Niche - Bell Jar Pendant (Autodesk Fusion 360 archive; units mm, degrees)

design "Bell Jar" references "Niche - Chief Architect - Luxe Single Pendant Cordset", "Bell Jar", "Luxe Single Pendant Cordset - 4ft Standard"
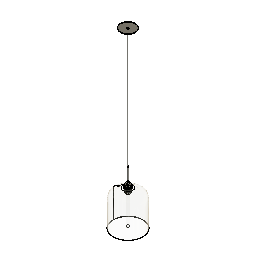
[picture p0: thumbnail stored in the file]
external_derived "ExternalDerived1"
external_derived "ExternalDerived2" bodies "Socket Body", "Shade Ring", "Shade Ring +Collar", "Socket", "Body1", "Metal Strain Relief", "Fabric Cord (1)", "Stem (Threaded)"
move "Move1"
external_derived "ExternalDerived3" bodies "T8-Bulb"
move "Move2"
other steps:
derived_base_feature "Derived Base Feature1" bodies "Bell Jar"
derived_base_feature "Derived Base Feature2" bodies "Socket Body", "Shade Ring", "Shade Ring +Collar", "Socket", "Body1", "Metal Strain Relief", "Fabric Cord (1)", "Stem (Threaded)"
derived_base_feature "Derived Base Feature3" bodies "T8-Bulb"
named bodies: "Bell Jar", "Socket Body", "Shade Ring", "Shade Ring +Collar", "Socket", "Body1", "Metal Strain Relief", "Fabric Cord (1)", "Stem (Threaded)", "Cap (Threaded)", "T8-Bulb"

design "Luxe Single Pendant Cordset - 4ft Standard" references "Luxe Canopy - Single Pendant Cordset"
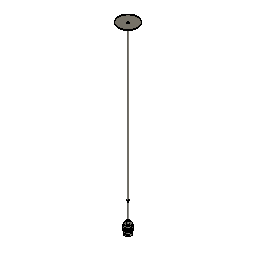
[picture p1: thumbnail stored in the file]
external_derived "ExternalDerived2" bodies "Cap (Threaded)"
move "Move1"
move "Move2"
offset_faces "OffsetFaces1" distance 1051.56
move "Move3"
move "Move4"
move "Move5"
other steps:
derived_base_feature "Derived Base Feature9" bodies "Socket Body", "Shade Ring", "Shade Ring +Collar", "Socket"
derived_base_feature "Derived Base Feature10" bodies "Body1"
derived_base_feature "Derived Base Feature12" bodies "Metal Strain Relief"
derived_base_feature "Derived Base Feature13" bodies "Fabric Cord (1)"
derived_base_feature "Derived Base Feature14" bodies "Stem (Threaded)"
derived_base_feature "Derived Base Feature15" bodies "Cap 9Threaded)", "Cap (Threaded)"
named bodies: "Socket Body", "Shade Ring", "Shade Ring +Collar", "Socket", "Metal Strain Relief", "Fabric Cord (1)", "Stem (Threaded)", "Cap 9Threaded)", "Body1", "Cap (Threaded)", "5M Set Screw"

design "Luxe Canopy - Single Pendant Cordset" references "M5 Set Screw", "Plastic Strain Relief", "Canopy Mounting Bar", "Canopy Mounting Bar Screw", "Luxe Cordset"
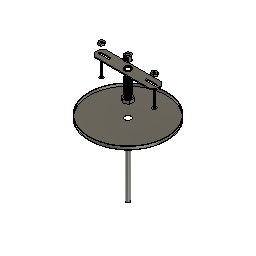
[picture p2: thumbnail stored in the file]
sketch "Sketch1" plane through (0, 0, 0) normal (0, 0, 1) x axis (1, 0, 0)
  circle C1 centre (0, 0) radius 63.5
  point P1 (0, 0)
  point P2 (0, 0)
  coincident P1 P2
  dimension "d1" diameter C1 = 127
extrude "Extrude1" new body sketch "Sketch1" along normal blind 5.08
shell "Shell1" innerThickness 0.762
hole "Hole1" HoleDepth 35.56 HoleDiameter 10.16 TipAngle 118
component_from_bodies "Body->Comp1"
component_insert "Component Insert1"
component_insert "Component Insert2"
component_insert "Component Insert3"
sketch "Sketch2" plane through (0, 0, 0) normal (0, 0, 1) x axis (1, 0, 0)
  circle C1 centre (0, 0) radius 3.175
  point P1 (0, 0)
  point P2 (0, 0)
  coincident P1 P2
  dimension "d8" diameter C1 = 6.35
extrude "Extrude2" new body sketch "Sketch2" along normal blind 127 and against normal blind 127 bodies "Fabric Cord"
component_insert "Component Insert4"
component_insert "Component Insert5"
position "Position1"
sketch "Sketch3" plane through (0, 0, 0.762) normal (0, 0, 1) x axis (-1, 0, 0)
  circle C1 centre (-0.0475, 0.2257) radius 5.08
  circle C2 centre (0, 0) radius 62.738
  circle C3 centre (0, 0) radius 4.826
  concentric C2 C3
  dimension "d13" diameter C3 = 9.652
extrude "Extrude3" new body sketch "Sketch3" profile of C3 along normal blind 25.4 bodies "Threaded Nipple"
shell "Shell2" innerThickness 1.27
thread "Thread1"
sketch "Sketch5" plane through (0, 0, 127) normal (0, 0, 1) x axis (-1, 0, 0)
  line L1 (-6.8191, 3.937) -> (0, 7.874)
  line L2 (-6.8191, -3.937) -> (-6.8191, 3.937)
  line L3 (0, -7.874) -> (-6.8191, -3.937)
  line L4 (6.8191, -3.937) -> (0, -7.874)
  line L5 (6.8191, 3.937) -> (6.8191, -3.937)
  line L6 (0, 7.874) -> (6.8191, 3.937)
  circle C1 centre (0, 0) radius 3.175
  point P2 (0, 0)
  point P9 (0, 0)
  point P3 (0, 7.874)
  coincident P2 P9
  dimension "d20" distance P3 P9 = 7.874
extrude "Extrude4" new body sketch "Sketch5" along normal blind 5.08 bodies "Hex Nut"
move "Move1"
thread "Thread2"
move "Move2" TranslateX 0 TranslateY 0 TranslateZ -55.88
move "Move3" TranslateX 0 TranslateY 0 TranslateZ 60.96
position "Position2"
sketch "Sketch6" plane through (0, 0, 0) normal (0, 0, 1) x axis (1, 0, 0)
  circle C1 centre (0, 0) radius 9.525
  point P1 (0, 0)
  point P2 (0, 0)
  coincident P1 P2
  dimension "d29" diameter C1 = 19.05
extrude "Extrude5" new body sketch "Sketch6" along normal blind 16.129 bodies "Metal Strain Relief"
move "Move4" TranslateX 0 TranslateY 0 TranslateZ -86.36
hole "Hole2" HoleDepth 10.16 HoleDiameter 5.08 TipAngle 118
hole "Hole3" HoleDepth 4.064 HoleDiameter 7.62 TipAngle 180
hole "Hole4" HoleDepth 12.192 HoleDiameter 9.144 TipAngle 180
thread "Thread3" ThreadOffset 0 ThreadLength 6.096
move "Move1" TranslateX 0 TranslateY 0 TranslateZ 68.58
move "Move5" TranslateX 0 TranslateY 0 TranslateZ 138.43
component_insert "Component Insert6"
external_derived "ExternalDerived1" bodies "5M Set Screw"
move "Move6" TranslateX 0 TranslateY 0 TranslateZ -185.42
copy_paste_bodies "CopyPasteBodies1"
move "Move7" TranslateX 0 TranslateY 0 TranslateZ -12.7
offset_faces "OffsetFaces1" distance -152.4
move "Move8"
component_from_bodies "Body->Comp2"
component_from_bodies "Body->Comp3"
component_from_bodies "Body->Comp4"
component_from_bodies "Body->Comp5"
hole "Hole1" HoleDepth 25.4 HoleDiameter 6.35 TipAngle 180
sketch "Sketch7" plane through (0, 0, 0) normal (0, 0, 1) x axis (1, 0, 0)
  line L1 (49.784, 3.9595) -> (52.07, 0)
  line L2 (45.212, 3.9595) -> (49.784, 3.9595)
  line L3 (42.926, 0) -> (45.212, 3.9595)
  line L4 (45.212, -3.9595) -> (42.926, 0)
  line L5 (49.784, -3.9595) -> (45.212, -3.9595)
  line L6 (52.07, 0) -> (49.784, -3.9595)
  point P2 (52.07, 0)
  point P8 (47.498, 0)
  dimension "d63" distance P2 P8 = 4.572
extrude "Extrude6" new body sketch "Sketch7" along normal blind 3.175 bodies "Mounting Hex Nut"
hole "Hole5" HoleDepth 25.4 HoleDiameter 3.81 TipAngle 180
thread "Thread4"
move "Move9"
component_from_bodies "Body->Comp6"
copy_paste "CopyPaste1"
move "Move10"
derived_base_feature "Derived Base Feature3" bodies "Stem (Threaded)", "Cap 9Threaded)"
move "Move11"
component_from_bodies "Body->Comp7"
component_from_bodies "Body->Comp8"
component_from_bodies "Body->Comp9"
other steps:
base_feature "Base Feature1"
base_feature "Base Feature1" bodies "Stem (Threaded)"
base_feature "Base Feature1" bodies "Cap 9Threaded)"
base_feature "Base Feature1" bodies "Fabric Cord"
base_feature "Base Feature1" bodies "Metal Strain Relief"
base_feature "Base Feature1" bodies "Mounting Hex Nut"
base_feature "Base Feature1" bodies "Hex Nut"
base_feature "Base Feature1" bodies "Fabric Cord (1)"
base_feature "Base Feature1" bodies "Threaded Nipple"
derived_base_feature "Derived Base Feature1" bodies "Socket Body", "Shade Ring", "Shade Ring +Collar", "Socket", "Rigid Stem"
derived_base_feature "Derived Base Feature2" bodies "5M Set Screw"
base_feature "Base Feature1" bodies "Fabric Cord", "Fabric Cord (1)"
create_component "CreateComponent1"
remove_body "RemoveBody1"
create_component "CreateComponent2"
remove_body "RemoveBody2"
create_component "CreateComponent3"
remove_body "RemoveBody3"
create_component "CreateComponent4"
remove_body "RemoveBody4"
create_component "CreateComponent5"
remove_body "RemoveBody5"
create_component "CreateComponent6"
remove_body "RemoveBody6"
create_component "CreateComponent7"
remove_body "RemoveBody7"
create_component "CreateComponent8"
remove_body "RemoveBody8"
create_component "CreateComponent9"
remove_body "RemoveBody9"
named bodies: "Fabric Cord", "Threaded Nipple", "Hex Nut", "Metal Strain Relief", "Socket Body", "Shade Ring", "Shade Ring +Collar", "Socket", "Rigid Stem", "5M Set Screw", "Fabric Cord (1)", "Mounting Hex Nut", "Stem (Threaded)", "Cap 9Threaded)"

design "M5 Set Screw"
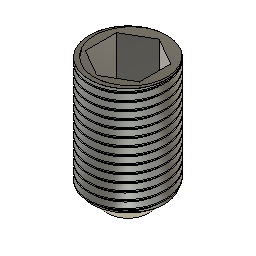
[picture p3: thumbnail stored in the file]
sketch "Sketch1" plane through (0, 0, 0) normal (0, 0, 1) x axis (1, 0, 0)
  circle C1 centre (0, 0) radius 2.5
  point P1 (0, 0)
  point P2 (0, 0)
  coincident P1 P2
  dimension "d1" diameter C1 = 5
extrude "Extrude1" new body sketch "Sketch1" along normal blind 8
sketch "Sketch2" plane through (0, 0, 8) normal (0, 0, 1) x axis (-1, 0, 0)
  line L1 (-1.7321, 1) -> (0, 2)
  line L2 (-1.7321, -1) -> (-1.7321, 1)
  line L3 (0, -2) -> (-1.7321, -1)
  line L4 (1.7321, -1) -> (0, -2)
  line L5 (1.7321, 1) -> (1.7321, -1)
  line L6 (0, 2) -> (1.7321, 1)
  circle C1 centre (0, 0) radius 2.5
  point P2 (0, 0)
  point P9 (0, 0)
  coincident P2 P9
extrude "Extrude2" cut sketch "Sketch2" profile of L1 L2 L3 L4 L5 L6 against normal blind 3
thread "Thread1" ThreadOffset 0.99 ThreadLength 7
chamfer "Chamfer1" distance 1.15

design "Luxe Cordset" references "M5 Set Screw"
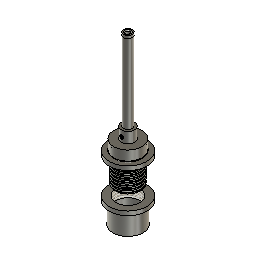
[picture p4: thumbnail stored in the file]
sketch "Sketch1" plane through (0, 0, 0) normal (0, 0, 1) x axis (1, 0, 0)
  circle C1 centre (0, 0) radius 20.6
  point P1 (0, 0)
  point P2 (0, 0)
  coincident P1 P2
  dimension "d11" diameter C1 = 41.2
extrude "Extrude1" new body sketch "Sketch1" along normal blind 14 bodies "Socket Body"
sketch "Sketch2" plane through (0, 0, 14) normal (0, 0, 1) x axis (-1, 0, 0)
  circle C1 centre (0, 0) radius 20.6
  circle C2 centre (0, 0) radius 9.6
  concentric C1 C2
  dimension "d3" diameter C2 = 19.2
extrude "Extrude2" add sketch "Sketch2" profile of C2 along normal blind 15.75
sketch "Sketch3" plane through (0, 0, 29.75) normal (0, 0, 1) x axis (-1, 0, 0)
  circle C1 centre (0, 0) radius 9.6
  circle C2 centre (0, 0) radius 5.75
  concentric C1 C2
  dimension "d6" diameter C2 = 11.5
extrude "Extrude3" new body sketch "Sketch3" profile of C2 along normal blind 114 bodies "Rigid Stem"
move "Move1"
sketch "Sketch4" plane through (0, 0, 203.75) normal (0, 0, 1) x axis (-1, 0, 0)
  circle C1 centre (0, 0) radius 5.75
  circle C2 centre (0, 0) radius 27.5
  dimension "d10" diameter C2 = 55
extrude "Extrude4" new body sketch "Sketch4" profile of C2 along normal blind 6 bodies "Shade Ring"
hole "Hole1" HoleDepth 25 HoleDiameter 42.75 TipAngle 118
sketch "Sketch5" plane through (0, 0, 0) normal (0, 0, 1) x axis (1, 0, 0)
  circle C1 centre (0, 0) radius 22
  point P1 (0, 0)
  point P2 (0, 0)
  coincident P1 P2
  dimension "d18" diameter C1 = 44
move "Move2"
copy_paste_bodies "CopyPasteBodies1"
move "Move3"
sketch "Sketch6" plane through (0, 0, 60) normal (0, 0, -1) x axis (1, 0, 0)
  circle C1 centre (0, 0) radius 20.6
  circle C2 centre (0, 0) radius 21.375
  circle C3 centre (0, 0) radius 20
  concentric C1 C2
  concentric C1 C3
  dimension "d21" diameter C2 = 42.75
  dimension "d24" diameter C3 = 40
cylinder_primitive "CylinderPrimitive1" Height 8 Diameter 42.75
thread "Thread1"
thread "Thread3"
hole "Hole2" HoleDepth 18 HoleDiameter 39 TipAngle 180
move "Move4"
move "Move5"
move "Move6"
hole "Hole3" HoleDepth 114 HoleDiameter 7.6 TipAngle 180
derived_base_feature "Derived Base Feature" bodies "Socket"
move "Move7"
scale "Scale1" ScaleX 1.2 ScaleY 1.2
move "Move8"
sketch "Sketch8" plane through (0, 0, -23.9827) normal (0, 0, -1) x axis (1, 0, 0)
  circle C1 centre (0, -0.036) radius 27.5
  circle C2 centre (0, -0.036) radius 22
  circle C3 centre (0, -0.036) radius 19.5
  dimension "d36" diameter C2 = 44
  dimension "d42" = -2.5
extrude "Extrude7" add sketch "Sketch8" profile of C2 C3 along normal blind 30
offset_faces "OffsetFaces1" distance 2.75
offset_faces "OffsetFaces2" distance -9
thread "Thread2"
move "Move9"
move "Move10"
move "Move11"
scale "Scale2" ScaleZ 1.2
move "Move12"
move "Move13"
move "Move14"
move "Move15"
move "Move16"
split_face "SplitFace1"
move "Move17"
move "Move18"
move "Move19"
move "Move20"
move "Move21"
move "Move22"
move "Move23"
move "Move24"
move "Move25"
move "Move26"
move "Move27"
thread "Thread4"
move "Move28"
move "Move29"
move "Move30"
hole "Hole4" HoleDepth 21 HoleDiameter 39.35 TipAngle 180
hole "Hole5" HoleDepth 9 HoleDiameter 5 TipAngle 180
move "Move31"
move "Move32"
hole "Hole6" HoleDepth 20 HoleDiameter 10 TipAngle 180
move_face "MoveFace3"
move "Move33"
move "Move34"
move "Move35"
move "Move36"
move "Move37"
thread "Thread5" ThreadOffset 0 ThreadLength 6
thread "Thread6" ThreadOffset 0 ThreadLength 6
move "Move38"
move "Move39"
move "Move40"
move "Move41"
component_insert "Component Insert"
thread "Thread7" ThreadOffset 0.5 ThreadLength 5.337
chamfer "Chamfer1" distance 0.5 distance 0.35
sketch "Sketch12" plane through (0, 0, 0) normal (0, 0, 1) x axis (1, 0, 0)
  circle C1 centre (0, 0) radius 6.35
  dimension "d60" diameter C1 = 12.7
extrude "Extrude8" new body sketch "Sketch12" along normal blind 115 bodies "Stem (Threaded)"
hole "Hole7" HoleDepth 115 HoleDiameter 9.65 TipAngle 118
thread "Thread8" ThreadOffset 0 ThreadLength 12.5
thread "Thread9" ThreadOffset 0 ThreadLength 12.5
sketch "Sketch13" plane through (0, 0, 0) normal (0, 0, 1) x axis (1, 0, 0)
  circle C1 centre (0, 0) radius 6.35
  point P1 (0, 0)
  point P2 (0, 0)
  coincident P1 P2
  dimension "d70" diameter C1 = 12.7
extrude "Extrude9" new body sketch "Sketch13" along normal blind 4 bodies "Cap 9Threaded)"
sketch "Sketch14" plane through (0, 0, 4) normal (0, 0, 1) x axis (-1, 0, 0)
  circle C1 centre (0, 0) radius 6.35
  circle C2 centre (0, 0) radius 4.5
  concentric C1 C2
  dimension "d73" diameter C2 = 9
extrude "Extrude10" add sketch "Sketch14" profile of C2 against normal blind 14
thread "Thread10"
hole "Hole8" HoleDepth 115 HoleDiameter 6.5 TipAngle 118 CSDiameter 9 CSAngle 90
move "Move42"
move "Move43"
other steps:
base_feature "Base Feature" bodies "Shade Ring +Collar"
named bodies: "Socket Body", "Shade Ring", "Shade Ring +Collar", "Socket", "Rigid Stem", "Stem (Threaded)", "Cap 9Threaded)"

design "Niche - Chief Architect - Luxe Single Pendant Cordset"
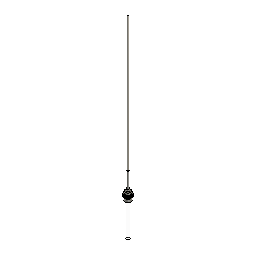
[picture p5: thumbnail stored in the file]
derived_base_feature "Derived Base Feature" bodies "Socket Body", "Shade Ring", "Shade Ring +Collar", "Socket", "Canopy", "Metal Strain Relief", "Fabric Cord (1)", "Stem (Threaded)"
remove_body "RemoveBody1"
remove_body "RemoveBody2"
split "Split1" bodies "Socket Body (1)"
remove_body "RemoveBody3"
align "Align1"
hole "Hole1" HoleDepth 19.05 HoleDiameter 8.89 TipAngle 118
combine "Combine1" bodies "Shade Ring"
split "Split2" bodies "Socket (1)"
remove_body "RemoveBody4"
split "Split3" bodies "Fabric Cord (1) (1)"
remove_body "RemoveBody5"
combine "Combine2" bodies "Socket Body"
align "Align2"
combine "Combine3" bodies "Metal Strain Relief"
sketch "Sketch1" plane through (0, 0, 0) normal (0, 1, 0) x axis (1, 0, 0)
  line L1 (13.1098, 24.9049) -> (-12.2902, 24.9049)
  line L2 (18.1898, 37.1766) -> (18.1898, 29.9849)
  line L3 (-17.3702, 29.9849) -> (-17.3702, 36.7132)
  line L4 (0, 132.969) -> (0, 24.9049)
  arc A1 centre (0, 86.36) radius 46.609 clockwise from (-22.6031, 45.5985) to (23.276, 45.979)
  arc A2 centre (-27.5302, 36.7132) radius 10.16 clockwise from (-22.6031, 45.5985) to (-17.3702, 36.7132)
  arc A3 centre (28.3498, 37.1766) radius 10.16 clockwise from (18.1898, 37.1766) to (23.276, 45.979)
  arc A4 centre (-12.2902, 29.9849) radius 5.08 clockwise from (-12.2902, 24.9049) to (-17.3702, 29.9849)
  arc A5 centre (13.1098, 29.9849) radius 5.08 clockwise from (18.1898, 29.9849) to (13.1098, 24.9049)
  point P5 (18.1898, 43.4469)
  point P3 (-17.3702, 24.9049)
  point P4 (18.1898, 24.9049)
  point P18 (0, 24.9049)
  point P19 (0, 132.969)
  horizontal L1
  vertical L2
  vertical L3
  tangent A1 A2
  tangent L3 A2
  coincident P5 L2
  coincident P5 A1
  tangent L2 A3
  tangent A1 A3
  equal A2 A3
  coincident P3 L1
  coincident P3 L3
  tangent L1 A4
  tangent L3 A4
  coincident P4 L1
  coincident P4 L2
  tangent L1 A5
  tangent L2 A5
  coincident L1 P18
  coincident A1 P19
  perpendicular L1 L4
  dimension "d4" diameter A1 = 93.218
  dimension "d5" distance P3 P4 = 35.56
  dimension "d6" distance P4 P5 = 18.542
  dimension "d7" radius A2 = 10.16
  dimension "d8" radius A4 = 5.08
  dimension "d9" radius A5 = 5.08
revolve "Revolve1" sketch "Sketch1" AlongAngle 360 bodies "G30-Bulb"
move "Move1"
sketch "Sketch2" plane through (0, 0, 0) normal (0, 1, 0) x axis (1, 0, 0)
  line L1 (12.7, 0) -> (-12.7, 0)
  line L2 (12.7, 152.4) -> (12.7, 0)
  line L3 (-12.7, 0) -> (-12.7, 152.4)
  line L4 (0, 165.1) -> (0, 0)
  arc A1 centre (0, 152.4) radius 12.7 clockwise from (-12.7, 152.4) to (12.7, 152.4)
  point P1 (0, 0)
  point P7 (0, 0)
  point P8 (0, 165.1)
  horizontal L1
  vertical L2
  vertical L3
  coincident P1 P7
  midpoint A1 P8
  perpendicular L1 L4
revolve "Revolve2" sketch "Sketch2" AlongAngle 360 bodies "T9-Bulb"
move "Move2"
sketch "Sketch3" plane through (0, 0, 0) normal (0, 1, 0) x axis (1, 0, 0)
  line L1 (12.7, 0) -> (-12.7, 0)
  line L2 (12.7, 254) -> (12.7, 0)
  line L3 (-12.7, 0) -> (-12.7, 254)
  line L4 (0, 266.7) -> (0, 0)
  arc A1 centre (0, 254) radius 12.7 clockwise from (-12.7, 254) to (12.7, 254)
  point P1 (0, 0)
  point P7 (0, 0)
  point P8 (0, 266.7)
  horizontal L1
  vertical L2
  vertical L3
  coincident P1 P7
  midpoint A1 P8
  perpendicular L1 L4
revolve "Revolve3" sketch "Sketch3" AlongAngle 360 bodies "T8-Bulb"
move "Move3"
move "Move4"
move "Move5"
sketch "Sketch4" plane through (0, 0, 0) normal (0, 1, 0) x axis (1, 0, 0)
  line L1 (15.875, -8.763) -> (-15.875, -8.763)
  line L2 (15.875, 22.987) -> (15.875, -8.763)
  line L3 (-15.875, 22.987) -> (15.875, 22.987)
  line L4 (-15.875, -8.763) -> (-15.875, 22.987)
  line L5 (0, 22.987) -> (0, -8.763)
  point P6 (0, -8.763)
  point P7 (0, 22.987)
  point P2 (-15.875, -8.763)
  point P3 (15.875, -8.763)
  point P5 (-15.875, 22.987)
  horizontal L1
  vertical L2
  horizontal L3
  vertical L4
  midpoint L1 P6
  midpoint L3 P7
  dimension "d13" distance P2 P3 = 31.75
  dimension "d14" distance P2 P5 = 31.75
revolve "Revolve4" sketch "Sketch4" AlongAngle 360 bodies "Bulb Extender"
move "Move6"
sketch "Sketch5" plane through (0, 0, 0) normal (0, 1, 0) x axis (1, 0, 0)
  line L1 (-12.7, 35.56) -> (12.7, 35.56)
  line L2 (-12.7, 5.08) -> (-12.7, 35.56)
  line L3 (12.7, 5.08) -> (-12.7, 5.08)
  line L4 (12.7, 35.56) -> (12.7, 5.08)
  line L5 (-12.7, 5.08) -> (12.7, 35.56)
  line L6 (12.7, 5.08) -> (-12.7, 35.56)
  line L7 (0, 35.56) -> (0, 5.08)
  point P6 (0, 20.32)
  point P7 (0, 5.08)
  point P8 (0, 35.56)
  horizontal L1
  perpendicular L1 L2
  parallel L1 L3
  parallel L2 L4
  coincident L5 P6
  coincident L6 P6
  midpoint L3 P7
  midpoint L1 P8
revolve "Revolve5" sketch "Sketch5" AlongAngle 360 bodies "Y-Spliter"
sketch "Sketch6" plane through (0, 0, 0) normal (0, 1, 0) x axis (1, 0, 0)
  line L1 (-55.88, 64.9514) -> (-21.59, 64.9514)
  line L2 (-55.88, 35.7414) -> (-55.88, 64.9514)
  line L3 (-21.59, 35.7414) -> (-55.88, 35.7414)
  line L4 (-21.59, 64.9514) -> (-21.59, 35.7414)
  line L5 (-55.88, 35.7414) -> (-21.59, 64.9514)
  line L6 (-21.59, 35.7414) -> (-55.88, 64.9514)
  line L7 (-38.735, 64.9514) -> (-38.735, 35.7414)
  point P6 (-38.735, 50.3464)
  point P7 (-38.735, 35.7414)
  point P8 (-38.735, 64.9514)
  point P4 (-55.88, 35.7414)
  point P5 (-21.59, 35.7414)
  point P2 (-21.59, 64.9514)
  horizontal L1
  perpendicular L1 L2
  parallel L1 L3
  parallel L2 L4
  coincident L5 P6
  coincident L6 P6
  midpoint L3 P7
  midpoint L1 P8
  dimension "d17" distance P4 P5 = 34.29
  dimension "d18" distance P2 P5 = 29.21
revolve "Revolve6" sketch "Sketch6" AlongAngle 360
chamfer "Chamfer1" distance 7.62
move "Move7"
mirror "Mirror1" mirrorStitchTolerance 0.1016
move "Move8"
combine "Combine4"
move "Move9"
sketch "Sketch7" plane through (0, 0, 0) normal (0, 1, 0) x axis (1, 0, 0)
  line L1 (-15.24, 40.64) -> (-15.24, 48.1816)
  line L2 (12.7, 38.1) -> (-12.7, 38.1)
  line L3 (15.24, 48.1816) -> (15.24, 40.64)
  line L4 (0, 100.1623) -> (0, 38.1)
  arc A1 centre (0, 76.2) radius 23.9623 clockwise from (-19.7282, 62.5988) to (19.7282, 62.5988)
  arc A2 centre (-40.64, 48.1816) radius 25.4 clockwise from (-19.7282, 62.5988) to (-15.24, 48.1816)
  arc A3 centre (40.64, 48.1816) radius 25.4 clockwise from (15.24, 48.1816) to (19.7282, 62.5988)
  arc A4 centre (-12.7, 40.64) radius 2.54 clockwise from (-12.7, 38.1) to (-15.24, 40.64)
  arc A5 centre (12.7, 40.64) radius 2.54 clockwise from (15.24, 40.64) to (12.7, 38.1)
  point P15 (0, 38.1)
  point P16 (0, 100.1623)
  parallel L1 L3
  tangent A1 A2
  tangent L1 A2
  tangent A1 A3
  tangent L3 A3
  tangent L1 A4
  tangent L2 A4
  tangent L2 A5
  tangent L3 A5
  midpoint L2 P15
  midpoint A1 P16
  perpendicular L2 L4
  dimension "d23" radius A2 = 25.4
  dimension "d24" radius A3 = 25.4
  dimension "d25" radius A4 = 2.54
  dimension "d26" radius A5 = 2.54
revolve "Revolve7" sketch "Sketch7" AlongAngle 360 bodies "A15-Bulb"
move "Move10"
copy_paste_bodies "CopyPasteBodies1"
copy_paste_bodies "CopyPasteBodies2"
move "Move11"
mirror "Mirror2" mirrorStitchTolerance 0.1016 bodies "A15-Bulb (1) (1)"
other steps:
base_feature "Base Feature1" bodies "Y-Spliter", "Bulb Extender", "Y-Spliter (1)", "Bulb Extender (1)"
base_feature "Base Feature2" bodies "A15-Bulb", "A15-Bulb (1)"
named bodies: "Socket Body", "Shade Ring", "Shade Ring +Collar", "Socket", "Canopy", "Metal Strain Relief", "Fabric Cord (1)", "Stem (Threaded)", "Adapter", "5M Set Screw", "Body1 (1)", "Socket Body (1)", "Socket (1)", "Fabric Cord (1) (1)", "G30-Bulb", "T9-Bulb", "T8-Bulb", "Bulb Extender", "Y-Spliter", "A15-Bulb", "Y-Spliter (1)", "Bulb Extender (1)", "A15-Bulb (1)", "A15-Bulb (1) (1)"

design "Bell Jar" references "Niche_BellJar_Single_Pendant"
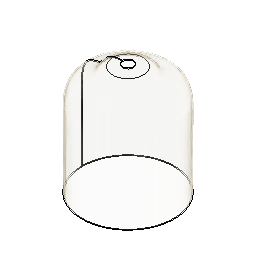
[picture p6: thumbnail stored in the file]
external_derived "ExternalDerived" bodies "Bell Jar"
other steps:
derived_base_feature "Derived Base Feature" bodies "Bell Jar"
named bodies: "Bell Jar"

design "Plastic Strain Relief"
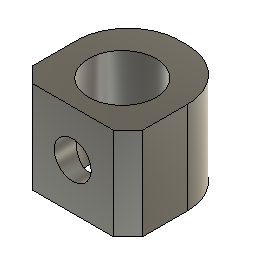
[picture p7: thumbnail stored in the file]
base_feature "Base Feature" bodies "strainrelief"
named bodies: "strainrelief"

design "Canopy Mounting Bar Screw"
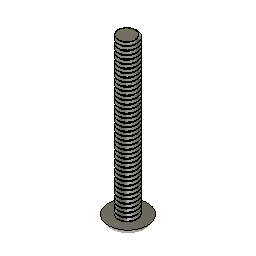
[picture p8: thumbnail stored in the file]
base_feature "Base Feature" bodies "screw1"
named bodies: "screw1"

design "Canopy Mounting Bar"
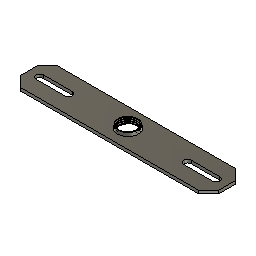
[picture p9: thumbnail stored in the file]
base_feature "Base Feature" bodies "mountingbar"
named bodies: "mountingbar"

design "Niche_BellJar_Single_Pendant"
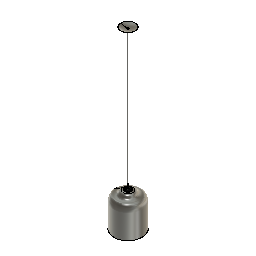
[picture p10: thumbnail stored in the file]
